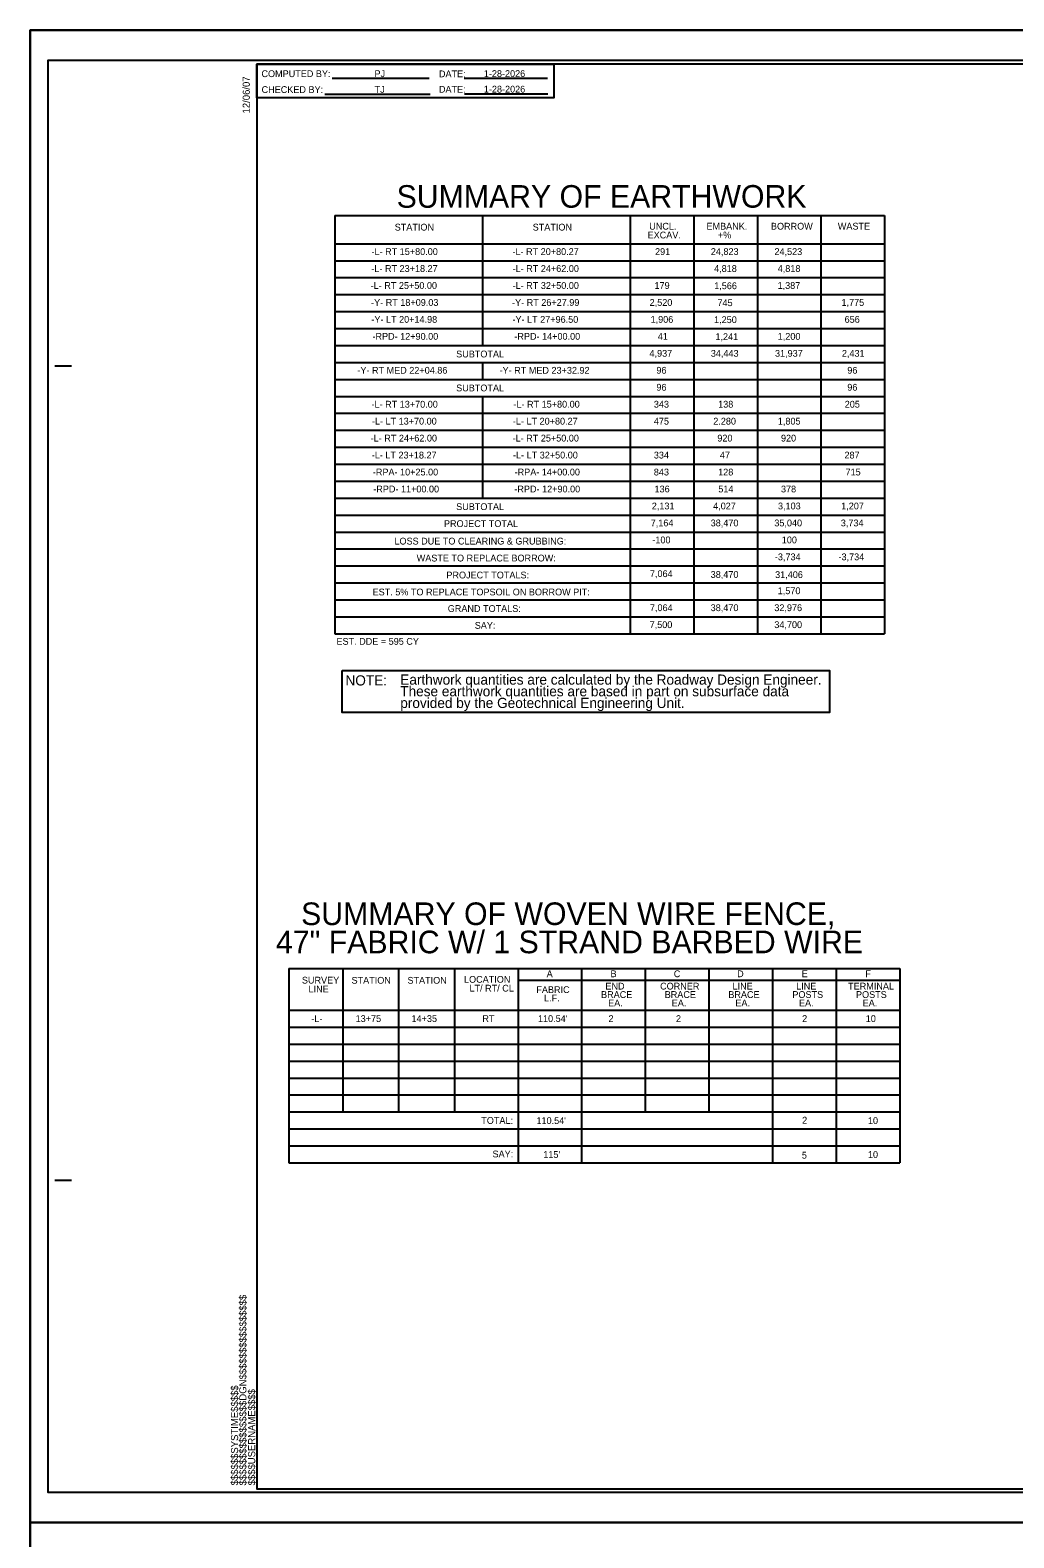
# Model space of a CAD drawing. Extents: x 1730642 to 1732326, y 538795 to 540995.
# Drawn here: x 1730642 to 1731367, y 539884 to 540995 of the extents above; entities that cross this region are included whole.
import ezdxf

# ---------------------------------------------------------------- set-up
doc = ezdxf.new("R2010")
doc.units = 0
for name, color, linetype in [('Old_Level_40', 7, 'Continuous'), ('Old_Level_44', 7, 'Continuous'), ('Sheet Cutting Line CELL', 7, 'Continuous'), ('Sheet Data Field CELL', 7, 'Continuous'), ('Sheet Pipe Summary CELL', 7, 'Continuous'), ('Sheet Pipe Summary Grid CELL', 7, 'Continuous'), ('Sheet Summary Combination CELL', 7, 'Continuous'), ('Sheet Summary Earthwork CELL', 7, 'Continuous'), ('Sheet Summary Guardrail CELL', 7, 'Continuous')]:
    doc.layers.add(name, color=color, linetype=linetype)

msp = doc.modelspace()

# ---------------------------------------------------------------- linework, layer by layer
at = {"layer": 'Old_Level_40'}
for p, q in [((1730864.2, 540960), (1730935.7, 540960)), ((1730961.5, 540959.9), (1731022.9, 540959.9)), ((1730858.7, 540948.3), (1730936.4, 540948.3)), ((1730961.7, 540948.4), (1731023.1, 540948.4)), ((1731016, 540858.8), (1731016, 540858.8)), ((1731022.3, 540858.7), (1731022.3, 540858.7)), ((1731031.3, 540858.9), (1731031.3, 540858.9)), ((1731036.9, 540858.8), (1731036.9, 540858.8)), ((1730659.6, 540747.9), (1730672.1, 540747.9)), ((1730659.6, 540147.9), (1730672.1, 540147.9)), ((1730808.5, 539920.4), (1730808.5, 539920.4))]:
    msp.add_line(p, q, dxfattribs=at)
for points in [[(1732308.5, 540970.4), (1730808.5, 540970.4), (1730808.5, 539920.4), (1732308.5, 539920.4)], [(1730808.5, 540970.4), (1731027.5, 540970.4), (1731027.5, 540945.4), (1730808.5, 540945.4)]]:
    msp.add_lwpolyline(points, close=True, dxfattribs=at)
at = {"layer": 'Old_Level_44'}
for p, q in [((1730866.1, 540858.8), (1730866.1, 540550.5)), ((1730866.1, 540858.8), (1731271.3, 540858.8)), ((1730974.8, 540858.8), (1730974.8, 540763)), ((1731083.7, 540858.8), (1731083.7, 540550.5)), ((1731130.6, 540858.8), (1731130.6, 540550.5)), ((1731177.5, 540858.8), (1731177.5, 540550.5)), ((1731224.4, 540858.8), (1731224.4, 540550.5)), ((1731271.3, 540858.8), (1731271.3, 540550.5)), ((1730866.1, 540838), (1731271.3, 540838)), ((1730866.1, 540825.5), (1731271.3, 540825.5)), ((1730866.1, 540813), (1731271.3, 540813)), ((1730866.1, 540800.5), (1731271.3, 540800.5)), ((1730866.1, 540788), (1731271.3, 540788)), ((1730866.1, 540775.5), (1731271.3, 540775.5)), ((1730866.1, 540763), (1731271.3, 540763)), ((1730866.1, 540750.5), (1731271.3, 540750.5)), ((1730974.8, 540750.5), (1730974.8, 540738)), ((1730866.1, 540738), (1731271.3, 540738)), ((1730866.1, 540725.5), (1731271.3, 540725.5)), ((1730974.8, 540725.5), (1730974.8, 540650.5)), ((1730866.1, 540713), (1731271.3, 540713)), ((1730866.1, 540700.5), (1731271.3, 540700.5)), ((1730866.1, 540688), (1731271.3, 540688)), ((1730866.1, 540675.5), (1731271.3, 540675.5)), ((1730866.1, 540663), (1731271.3, 540663)), ((1730866.1, 540650.5), (1731271.3, 540650.5)), ((1730866.1, 540638), (1731271.3, 540638)), ((1730866.1, 540625.5), (1731271.3, 540625.5)), ((1730866.1, 540613), (1731271.3, 540613)), ((1730866.1, 540600.5), (1731271.3, 540600.5)), ((1730866.1, 540588), (1731271.3, 540588)), ((1730866.1, 540575.5), (1731271.3, 540575.5)), ((1730866.1, 540563), (1731271.3, 540563)), ((1730866.1, 540550.5), (1731271.3, 540550.5))]:
    msp.add_line(p, q, dxfattribs=at)
at = {"layer": 'Sheet Cutting Line CELL'}
for points in [[(1730641.5, 540995.4), (1732325.5, 540995.4), (1732325.5, 539895.4), (1730641.5, 539895.4)], [(1730641.5, 539895.4), (1732325.5, 539895.4), (1732325.5, 538795.4), (1730641.5, 538795.4)]]:
    msp.add_lwpolyline(points, close=True, dxfattribs=at)
at = {"layer": 'Sheet Data Field CELL'}
msp.add_lwpolyline([(1730871.6, 540523.4), (1731230.7, 540523.4), (1731230.7, 540492.6), (1730871.6, 540492.6)], close=True, dxfattribs=at)
at = {"layer": 'Sheet Pipe Summary CELL'}
msp.add_lwpolyline([(1732321, 540973), (1730654.5, 540973), (1730654.5, 539917.9), (1732321, 539917.9)], close=True, dxfattribs=at)
at = {"layer": 'Sheet Pipe Summary Grid CELL'}
for p, q in [((1730832.1, 540303.7), (1731113.5, 540303.7)), ((1730832.1, 540303.7), (1730832.1, 540160.6)), ((1730871.9, 540303.7), (1730871.9, 540198.1)), ((1730913, 540303.7), (1730913, 540198.1)), ((1730954.2, 540303.7), (1730954.2, 540198.1)), ((1731001.1, 540303.7), (1731001.1, 540160.6)), ((1731048, 540303.7), (1731048, 540160.6)), ((1731094.9, 540303.7), (1731094.9, 540198.1)), ((1731113.5, 540303.7), (1731282.5, 540303.7)), ((1731141.8, 540303.7), (1731141.8, 540198.1)), ((1731188.7, 540303.7), (1731188.7, 540160.6)), ((1731235.6, 540303.7), (1731235.6, 540160.6)), ((1731282.5, 540303.7), (1731282.5, 540160.6)), ((1731001, 540295.1), (1731282.3, 540295.1)), ((1730832.1, 540273.1), (1731113.5, 540273.1)), ((1731113.5, 540273.1), (1731282.5, 540273.1)), ((1730832.1, 540260.6), (1731113.5, 540260.6)), ((1731113.5, 540260.6), (1731282.5, 540260.6)), ((1730832.1, 540248.1), (1731113.5, 540248.1)), ((1731113.5, 540248.1), (1731282.5, 540248.1)), ((1730832.1, 540235.6), (1731113.5, 540235.6)), ((1731113.5, 540235.6), (1731282.5, 540235.6)), ((1730832.1, 540223.1), (1731113.5, 540223.1)), ((1731113.5, 540223.1), (1731282.5, 540223.1)), ((1730832.1, 540210.6), (1731113.5, 540210.6)), ((1731113.5, 540210.6), (1731282.5, 540210.6)), ((1730832.1, 540198.1), (1731113.5, 540198.1)), ((1731113.5, 540198.1), (1731282.5, 540198.1)), ((1730832.1, 540185.6), (1731113.5, 540185.6)), ((1731113.5, 540185.6), (1731282.5, 540185.6)), ((1730832.1, 540173.1), (1731113.5, 540173.1)), ((1731113.5, 540173.1), (1731282.5, 540173.1)), ((1730832.1, 540160.6), (1731113.5, 540160.6)), ((1731113.5, 540160.6), (1731282.5, 540160.6))]:
    msp.add_line(p, q, dxfattribs=at)
for points in [[(1732325.5, 540995.4), (1730641.5, 540995.4), (1730641.5, 539895.4), (1732325.5, 539895.4)], [(1732325.5, 539895.4), (1730641.5, 539895.4), (1730641.5, 538795.4), (1732325.5, 538795.4)]]:
    msp.add_lwpolyline(points, close=True, dxfattribs=at)
at = {"layer": 'Sheet Summary Earthwork CELL'}
for p, q in [((1732325.5, 540995.4), (1730641.5, 540995.4)), ((1730641.5, 540995.4), (1730641.5, 539895.4)), ((1730641.5, 539895.4), (1732325.5, 539895.4)), ((1730641.5, 539895.4), (1730641.5, 538795.4))]:
    msp.add_line(p, q, dxfattribs=at)
at = {"layer": 'Sheet Summary Guardrail CELL'}
for p, q in [((1730966.2, 540303.7), (1730966.2, 540303.7)), ((1730972.5, 540303.6), (1730972.5, 540303.6)), ((1730988.7, 540303.8), (1730988.7, 540303.8)), ((1730994.3, 540303.7), (1730994.3, 540303.7))]:
    msp.add_line(p, q, dxfattribs=at)

# ---------------------------------------------------------------- texts
at = {"layer": 'Old_Level_40'}
for s, height, rotation, p in [('12/06/07', 5.25, 90, (1730803.4, 540934)), ('SUMMARY OF EARTHWORK', 16.667, 0.0119, (1730911.6, 540864.5)), ('$$$$$$$$$$$$$$$$DGN$$$$$$$$$$$$$$$$', 5.25, 90, (1730800.9, 539922.8)), ('$$$$$$SYSTIME$$$$$', 5.25, 90, (1730794.8, 539922.8)), ('$$$$USERNAME$$$$', 5.25, 90, (1730807.4, 539922.8))]:
    msp.add_text(s, height=height, rotation=rotation, dxfattribs=at).set_placement(p)
for s, p in [('COMPUTED BY:', (1730812, 540960.8)), ('PJ', (1730895.3, 540960.8)), ('DATE:', (1730942.8, 540960.7)), ('1-28-2026', (1730975.9, 540960.9)), ('CHECKED BY:', (1730812.1, 540949.1)), ('TJ', (1730895.4, 540949.2)), ('DATE:', (1730942.8, 540949.3)), ('1-28-2026', (1730975.9, 540949.4)), ('STATION', (1730910.2, 540847.7)), ('STATION', (1731011.9, 540847.7)), ('EXCAV.', (1731096.6, 540841.9)), ('UNCL.', (1731097.8, 540848.4)), ('EMBANK.', (1731140, 540848.4)), ('+%', (1731148.4, 540841.9)), ('BORROW', (1731187.5, 540848.4)), ('WASTE', (1731236.8, 540848.4)), ('-L- RT 15+80.00', (1730893.1, 540829.7)), ('-L- RT 20+80.27', (1730997, 540829.7)), ('291', (1731102.1, 540829.7)), ('24,823', (1731143.2, 540829.7)), ('24,523', (1731190.1, 540829.7)), ('-L- RT 23+18.27', (1730893, 540817.2)), ('-L- RT 24+62.00', (1730997.1, 540817.2)), ('4,818', (1731145.6, 540817.2)), ('4,818', (1731192.5, 540817.2)), ('-L- RT 25+50.00', (1730892.5, 540804.7)), ('-L- RT 32+50.00', (1730997.1, 540804.7)), ('179', (1731101.7, 540804.7)), ('1,566', (1731145.7, 540804.5)), ('1,387', (1731192.4, 540804.7)), ('-Y- RT 18+09.03', (1730892.8, 540792.2)), ('-Y- RT 26+27.99', (1730996.7, 540792.2)), ('2,520', (1731098.1, 540792.2)), ('745', (1731148.1, 540792)), ('1,775', (1731239.5, 540792.2)), ('-Y- LT 20+14.98', (1730893, 540779.7)), ('-Y- LT 27+96.50', (1730997, 540779.7)), ('1,906', (1731098.8, 540779.7)), ('1,250', (1731145.6, 540779.5)), ('656', (1731241.8, 540779.7)), ('-RPD- 12+90.00', (1730893.8, 540767.2)), ('-RPD- 14+00.00', (1730998.4, 540767.2)), ('41', (1731104.1, 540767.2)), ('1,241', (1731146.6, 540767)), ('1,200', (1731192.5, 540767.2)), ('SUBTOTAL', (1730955.5, 540754.2)), ('4,937', (1731098, 540754.7)), ('34,443', (1731143.2, 540754.7)), ('31,937', (1731190.5, 540754.7)), ('2,431', (1731239.8, 540754.7)), ('-Y- RT MED 22+04.86', (1730882.7, 540742.2)), ('-Y- RT MED 23+32.92', (1730987.5, 540742.2)), ('96', (1731103.1, 540742.2)), ('96', (1731243.8, 540742.2)), ('SUBTOTAL', (1730955.5, 540729.2)), ('96', (1731103.1, 540729.7)), ('96', (1731243.8, 540729.7)), ('-L- RT 13+70.00', (1730893.1, 540717.2)), ('-L- RT 15+80.00', (1730997.7, 540717.2)), ('343', (1731101.2, 540717.2)), ('138', (1731148.6, 540717.2)), ('205', (1731241.9, 540717.2)), ('-L- LT 13+70.00', (1730893.4, 540704.7)), ('-L- LT 20+80.27', (1730997.3, 540704.7)), ('475', (1731101.2, 540704.7)), ('2.280', (1731145, 540704.7)), ('1,805', (1731192.6, 540704.7)), ('-L- RT 24+62.00', (1730892.5, 540692.2)), ('-L- RT 25+50.00', (1730997.1, 540692.2)), ('920', (1731148, 540692.2)), ('920', (1731194.9, 540692.2)), ('-L- LT 23+18.27', (1730893.3, 540679.7)), ('-L- LT 32+50.00', (1730997.4, 540679.7)), ('334', (1731101.2, 540679.7)), ('47', (1731149.9, 540679.7)), ('287', (1731241.7, 540679.7)), ('-RPA- 10+25.00', (1730894.1, 540667.2)), ('-RPA- 14+00.00', (1730998.6, 540667.2)), ('843', (1731101.2, 540667.2)), ('128', (1731148.6, 540667.2)), ('715', (1731242.5, 540667.2)), ('-RPD- 11+00.00', (1730894.4, 540654.7)), ('-RPD- 12+90.00', (1730998.4, 540654.7)), ('136', (1731101.7, 540654.7)), ('514', (1731148.7, 540654.7)), ('378', (1731194.9, 540654.7)), ('SUBTOTAL', (1730955.5, 540641.7)), ('2,131', (1731099.7, 540642.2)), ('4,027', (1731144.9, 540642.2)), ('3,103', (1731192.7, 540642.2)), ('1,207', (1731239.3, 540642.2)), ('PROJECT TOTAL', (1730946.5, 540629.2)), ('7,164', (1731098.9, 540629.7)), ('38,470', (1731143.1, 540629.7)), ('35,040', (1731190, 540629.7)), ('3,734', (1731239, 540629.7)), ('-100', (1731100.1, 540617.2)), ('100', (1731195.5, 540617.2)), ('LOSS DUE TO CLEARING & GRUBBING:', (1730910, 540616.3)), ('WASTE TO REPLACE BORROW:', (1730926.4, 540603.8)), ('-3,734', (1731190.4, 540604.7)), ('-3,734', (1731237.3, 540604.7)), ('PROJECT TOTALS:', (1730948.3, 540591.3)), ('7,064', (1731098.3, 540592.3)), ('38,470', (1731143.1, 540591.7)), ('31,406', (1731190.6, 540591.6)), ('EST. 5% TO REPLACE TOPSOIL ON BORROW PIT:', (1730893.9, 540578.8)), ('1,570', (1731192.5, 540579.7)), ('GRAND TOTALS:', (1730949.3, 540566.6)), ('7,064', (1731098.3, 540567.2)), ('38,470', (1731143.1, 540567.2)), ('32,976', (1731190, 540567.2)), ('SAY:', (1730969.2, 540554.2)), ('7,500', (1731098.1, 540554.7)), ('34,700', (1731190, 540554.7))]:
    msp.add_text(s, height=5, dxfattribs=at).set_placement(p)
at = {"layer": 'Sheet Data Field CELL'}
for s, p in [('NOTE:', (1730873.9, 540512.4)), ('These earthwork quantities are based in part on subsurface data ', (1730914.3, 540504.4)), ('Earthwork quantities are calculated by the Roadway Design Engineer. ', (1730914.3, 540513)), ('provided by the Geotechnical Engineering Unit.', (1730914.3, 540495.8))]:
    msp.add_text(s, height=7.5, dxfattribs=at).set_placement(p)
at = {"layer": 'Sheet Summary Combination CELL'}
msp.add_text('EST. DDE = 595 CY', height=5, rotation=0, dxfattribs=at).set_placement((1730867.3, 540542.4))
at = {"layer": 'Sheet Summary Guardrail CELL'}
for s, p in [('SUMMARY OF WOVEN WIRE FENCE, ', (1730841.2, 540335.8)), ('47" FABRIC W/ 1 STRAND BARBED WIRE', (1730822.7, 540315))]:
    msp.add_text(s, height=16.667, rotation=0.0119, dxfattribs=at).set_placement(p)
for s, p in [('A', (1731022.2, 540297.4)), ('B', (1731069.3, 540297.4)), ('C', (1731115.9, 540297.4)), ('D', (1731162.6, 540297.4)), ('E', (1731210.2, 540297.4)), ('F', (1731257.1, 540297.4)), ('SURVEY', (1730841.8, 540292.7)), ('LINE', (1730846.7, 540286.2)), ('STATION', (1730878.4, 540292.6)), ('STATION', (1730919.6, 540292.6)), ('LOCATION', (1730961.3, 540293.3)), ('LT/ RT/ CL', (1730965.3, 540286.8)), ('FABRIC', (1731014.6, 540285.7)), ('END', (1731065.5, 540288.3)), ('CORNER ', (1731105.8, 540288.3)), ('LINE ', (1731159.2, 540288.3)), ('LINE ', (1731206.1, 540288.3)), ('TERMINAL ', (1731244.4, 540288.3)), ('L.F.', (1731020.3, 540279.5)), ('BRACE', (1731062.3, 540282.1)), ('EA.', (1731067.5, 540275.9)), ('BRACE', (1731109.2, 540282.1)), ('EA.', (1731114.4, 540275.9)), ('BRACE ', (1731156.1, 540282.1)), ('EA.', (1731161.3, 540275.9)), ('POSTS', (1731203.3, 540282.1)), ('EA.', (1731208.2, 540275.9)), ('POSTS', (1731250.2, 540282.1)), ('EA.', (1731255.1, 540275.9)), ('-L-', (1730848.8, 540264.4)), ('13+75', (1730881.4, 540264.4)), ('14+35', (1730922.6, 540264.4)), ('RT', (1730974.8, 540264.4)), ("110.54'", (1731015.8, 540264.4)), ('2', (1731067.8, 540264.4)), ('2', (1731117.5, 540264.4)), ('2', (1731210.5, 540264.4)), ('10', (1731257.4, 540264.4)), ('TOTAL:', (1730974, 540189.3)), ("110.54'", (1731014.7, 540189.2)), ('2', (1731210.5, 540189.5)), ('10', (1731259, 540189.2)), ('SAY:', (1730982.3, 540164.6)), ("115'", (1731019.7, 540164.2)), ('5', (1731210.3, 540163.7)), ('10', (1731259, 540164.2))]:
    msp.add_text(s, height=5, dxfattribs=at).set_placement(p)

doc.saveas('drawing.dxf')
